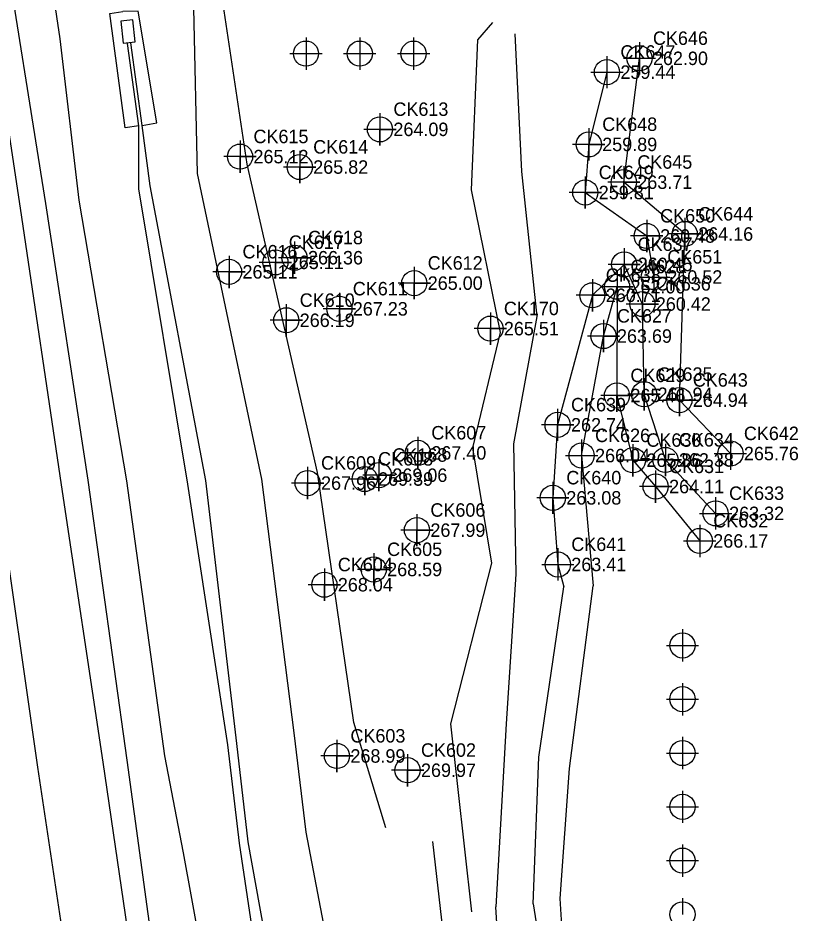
# Model space of a CAD drawing. Extents: x 1941547 to 1942851, y 663002 to 668358.
# Drawn here: x 1942636.4 to 1942781.5, y 663600.2 to 663766.6 of the extents above; entities that cross this region are included whole.
import ezdxf

# ---------------------------------------------------------------- set-up
doc = ezdxf.new("R2010")
doc.units = 0
for name, color, linetype in [('CTL GPS Vertical Cogo Elevation', 7, 'Continuous'), ('CTL NGS Vertical CELL', 7, 'Continuous'), ('Default Symbol CELL', 7, 'Continuous'), ('Exist DTM Breakline Cogo Elevation', 7, 'Continuous'), ('Exist DTM Breakline Cogo Number', 7, 'Continuous'), ('Exist DTM Breakline Cogo Point CELL', 7, 'Continuous'), ('Exist DTM Drainline Cogo Elevation', 7, 'Continuous'), ('Exist DTM QL2 LIDAR Elevation Point', 7, 'Continuous'), ('Exist Property Iron Pin Cogo Number', 7, 'Continuous'), ('Exist Roads EOP Cogo Elevation', 7, 'Continuous'), ('Exist Roads EOP Cogo Number', 7, 'Continuous'), ('Exist Roads EOP Cogo Point CELL', 7, 'Continuous'), ('Exist Roads EOT', 7, 'Continuous'), ('Exist Structure Minor Paved Ditch or Gutter', 7, 'Continuous'), ('Exist Utilities Telephone UG Cable SUE LOS C Cogo Elevation', 7, 'Continuous'), ('Exist Utilities Telephone UG FO SUE LOS C Cogo Elevation', 7, 'Continuous')]:
    doc.layers.add(name, color=color, linetype=linetype)

msp = doc.modelspace()

# ---------------------------------------------------------------- linework, layer by layer
at = {"layer": 'CTL NGS Vertical CELL'}
for points in [[(1942684.41, 663567.93), (1942677.62, 663613.22), (1942675.48, 663631.55), (1942668, 663679.97), (1942658.93, 663734.89), (1942658.92, 663746.56), (1942656.8, 663761.87)], [(1942691.99, 663527.43), (1942687.35, 663568.53), (1942679.24, 663613.49), (1942677.15, 663631.76), (1942671.36, 663680.68), (1942661.01, 663735.45), (1942659.52, 663746.66), (1942657.4, 663761.97)]]:
    msp.add_lwpolyline(points, dxfattribs=at)
at = {"layer": 'Exist DTM Breakline Cogo Number'}
for points in [[(1942752.01, 663762.12), (1942752.01, 663759.12)], [(1942745.96, 663759.55), (1942745.96, 663756.55)], [(1942749.01, 663759.12), (1942752.01, 663759.12)], [(1942752.01, 663759.12), (1942755.01, 663759.12)], [(1942752.01, 663759.12), (1942752.01, 663756.12)], [(1942742.96, 663756.55), (1942745.96, 663756.55)], [(1942745.96, 663756.55), (1942748.96, 663756.55)], [(1942745.96, 663756.55), (1942745.96, 663753.55)], [(1942754.68, 663721.47), (1942754.68, 663718.47)], [(1942751.68, 663718.47), (1942754.68, 663718.47)], [(1942754.68, 663718.47), (1942757.68, 663718.47)], [(1942754.68, 663718.47), (1942754.68, 663715.47)], [(1942741.25, 663688.29), (1942741.25, 663685.29)], [(1942768.92, 663688.66), (1942768.92, 663685.66)], [(1942738.25, 663685.29), (1942741.25, 663685.29)], [(1942741.25, 663685.29), (1942744.25, 663685.29)], [(1942741.25, 663685.29), (1942741.25, 663682.29)], [(1942765.92, 663685.66), (1942768.92, 663685.66)], [(1942768.92, 663685.66), (1942771.92, 663685.66)], [(1942768.92, 663685.66), (1942768.92, 663682.66)], [(1942766.17, 663677.54), (1942766.17, 663674.54)], [(1942763.17, 663674.54), (1942766.17, 663674.54)], [(1942766.17, 663674.54), (1942769.17, 663674.54)], [(1942766.17, 663674.54), (1942766.17, 663671.54)], [(1942763.22, 663672.42), (1942763.22, 663669.42)], [(1942760.22, 663669.42), (1942763.22, 663669.42)], [(1942763.22, 663669.42), (1942766.22, 663669.42)], [(1942763.22, 663669.42), (1942763.22, 663666.42)], [(1942736.83, 663668.05), (1942736.83, 663665.05)], [(1942733.83, 663665.05), (1942736.83, 663665.05)], [(1942736.83, 663665.05), (1942739.83, 663665.05)], [(1942736.83, 663665.05), (1942736.83, 663662.05)]]:
    msp.add_lwpolyline(points, dxfattribs=at)
for centre in [(1942752.01, 663759.12), (1942745.96, 663756.55), (1942754.68, 663718.47), (1942741.25, 663685.29), (1942768.92, 663685.66), (1942766.17, 663674.54), (1942763.22, 663669.42), (1942736.83, 663665.05)]:
    msp.add_circle(centre, 2.34, dxfattribs=at)
at = {"layer": 'Exist DTM Drainline Cogo Elevation'}
for points in [[(1942703.75, 663748.92), (1942703.75, 663742.92), (1942703.75, 663745.92), (1942706.75, 663745.92), (1942700.75, 663745.92)], [(1942703.75, 663748.92), (1942703.75, 663742.92), (1942703.75, 663745.92), (1942706.75, 663745.92), (1942700.75, 663745.92)], [(1942677.73, 663743.85), (1942677.73, 663737.85), (1942677.73, 663740.85), (1942680.73, 663740.85), (1942674.73, 663740.85)], [(1942677.73, 663743.85), (1942677.73, 663737.85), (1942677.73, 663740.85), (1942680.73, 663740.85), (1942674.73, 663740.85)], [(1942688.84, 663741.91), (1942688.84, 663735.91), (1942688.84, 663738.91), (1942691.84, 663738.91), (1942685.84, 663738.91)], [(1942688.84, 663741.91), (1942688.84, 663735.91), (1942688.84, 663738.91), (1942691.84, 663738.91), (1942685.84, 663738.91)], [(1942687.87, 663725.06), (1942687.87, 663719.06), (1942687.87, 663722.06), (1942690.87, 663722.06), (1942684.87, 663722.06)], [(1942687.87, 663725.06), (1942687.87, 663719.06), (1942687.87, 663722.06), (1942690.87, 663722.06), (1942684.87, 663722.06)], [(1942684.3, 663724.2), (1942684.3, 663718.2), (1942684.3, 663721.2), (1942687.3, 663721.2), (1942681.3, 663721.2)], [(1942684.3, 663724.2), (1942684.3, 663718.2), (1942684.3, 663721.2), (1942687.3, 663721.2), (1942681.3, 663721.2)], [(1942675.69, 663722.43), (1942675.69, 663716.43), (1942675.69, 663719.43), (1942678.69, 663719.43), (1942672.69, 663719.43)], [(1942675.69, 663722.43), (1942675.69, 663716.43), (1942675.69, 663719.43), (1942678.69, 663719.43), (1942672.69, 663719.43)], [(1942710.13, 663720.34), (1942710.13, 663714.34), (1942710.13, 663717.34), (1942713.13, 663717.34), (1942707.13, 663717.34)], [(1942710.13, 663720.34), (1942710.13, 663714.34), (1942710.13, 663717.34), (1942713.13, 663717.34), (1942707.13, 663717.34)], [(1942696.2, 663715.56), (1942696.2, 663709.56), (1942696.2, 663712.56), (1942699.2, 663712.56), (1942693.2, 663712.56)], [(1942696.2, 663715.56), (1942696.2, 663709.56), (1942696.2, 663712.56), (1942699.2, 663712.56), (1942693.2, 663712.56)], [(1942686.33, 663713.43), (1942686.33, 663707.43), (1942686.33, 663710.43), (1942689.33, 663710.43), (1942683.33, 663710.43)], [(1942686.33, 663713.43), (1942686.33, 663707.43), (1942686.33, 663710.43), (1942689.33, 663710.43), (1942683.33, 663710.43)], [(1942724.29, 663711.88), (1942724.29, 663705.88), (1942724.29, 663708.88), (1942727.29, 663708.88), (1942721.29, 663708.88)], [(1942710.8, 663688.78), (1942710.8, 663682.78), (1942710.8, 663685.78), (1942713.8, 663685.78), (1942707.8, 663685.78)], [(1942710.8, 663688.78), (1942710.8, 663682.78), (1942710.8, 663685.78), (1942713.8, 663685.78), (1942707.8, 663685.78)], [(1942703.55, 663684.64), (1942703.55, 663678.64), (1942703.55, 663681.64), (1942706.55, 663681.64), (1942700.55, 663681.64)], [(1942690.3, 663683.17), (1942690.3, 663677.17), (1942690.3, 663680.17), (1942693.3, 663680.17), (1942687.3, 663680.17)], [(1942700.91, 663683.93), (1942700.91, 663677.93), (1942700.91, 663680.93), (1942703.91, 663680.93), (1942697.91, 663680.93)], [(1942700.91, 663683.93), (1942700.91, 663677.93), (1942700.91, 663680.93), (1942703.91, 663680.93), (1942697.91, 663680.93)], [(1942710.63, 663674.42), (1942710.63, 663668.42), (1942710.63, 663671.42), (1942713.63, 663671.42), (1942707.63, 663671.42)], [(1942710.63, 663674.42), (1942710.63, 663668.42), (1942710.63, 663671.42), (1942713.63, 663671.42), (1942707.63, 663671.42)], [(1942702.59, 663667.12), (1942702.59, 663661.12), (1942702.59, 663664.12), (1942705.59, 663664.12), (1942699.59, 663664.12)], [(1942702.59, 663667.12), (1942702.59, 663661.12), (1942702.59, 663664.12), (1942705.59, 663664.12), (1942699.59, 663664.12)], [(1942693.42, 663664.28), (1942693.42, 663658.28), (1942693.42, 663661.28), (1942696.42, 663661.28), (1942690.42, 663661.28)], [(1942693.42, 663664.28), (1942693.42, 663658.28), (1942693.42, 663661.28), (1942696.42, 663661.28), (1942690.42, 663661.28)], [(1942695.76, 663632.45), (1942695.76, 663626.45), (1942695.76, 663629.45), (1942698.76, 663629.45), (1942692.76, 663629.45)], [(1942695.76, 663632.45), (1942695.76, 663626.45), (1942695.76, 663629.45), (1942698.76, 663629.45), (1942692.76, 663629.45)], [(1942708.88, 663629.8), (1942708.88, 663623.8), (1942708.88, 663626.8), (1942711.88, 663626.8), (1942705.88, 663626.8)], [(1942708.88, 663629.8), (1942708.88, 663623.8), (1942708.88, 663626.8), (1942711.88, 663626.8), (1942705.88, 663626.8)]]:
    msp.add_lwpolyline(points, dxfattribs=at)
for centre in [(1942703.75, 663745.92), (1942703.75, 663745.92), (1942677.73, 663740.85), (1942677.73, 663740.85), (1942688.84, 663738.91), (1942688.84, 663738.91), (1942687.87, 663722.06), (1942687.87, 663722.06), (1942684.3, 663721.2), (1942684.3, 663721.2), (1942675.69, 663719.43), (1942675.69, 663719.43), (1942710.13, 663717.34), (1942710.13, 663717.34), (1942696.2, 663712.56), (1942696.2, 663712.56), (1942686.33, 663710.43), (1942686.33, 663710.43), (1942724.29, 663708.88), (1942710.8, 663685.78), (1942710.8, 663685.78), (1942700.91, 663680.93), (1942700.91, 663680.93), (1942703.55, 663681.64), (1942690.3, 663680.17), (1942710.63, 663671.42), (1942710.63, 663671.42), (1942702.59, 663664.12), (1942702.59, 663664.12), (1942693.42, 663661.28), (1942693.42, 663661.28), (1942695.76, 663629.45), (1942695.76, 663629.45), (1942708.88, 663626.8), (1942708.88, 663626.8)]:
    msp.add_circle(centre, 2.34, dxfattribs=at)
at = {"layer": 'Exist DTM QL2 LIDAR Elevation Point'}
for points in [[(1942690, 663763), (1942690, 663760)], [(1942700, 663763), (1942700, 663760)], [(1942710, 663763), (1942710, 663760)], [(1942687, 663760), (1942690, 663760)], [(1942690, 663760), (1942693, 663760)], [(1942690, 663760), (1942690, 663757)], [(1942697, 663760), (1942700, 663760)], [(1942700, 663760), (1942703, 663760)], [(1942700, 663760), (1942700, 663757)], [(1942707, 663760), (1942710, 663760)], [(1942710, 663760), (1942713, 663760)], [(1942710, 663760), (1942710, 663757)], [(1942760, 663653), (1942760, 663650)], [(1942757, 663650), (1942760, 663650)], [(1942760, 663650), (1942763, 663650)], [(1942760, 663650), (1942760, 663647)], [(1942760, 663643), (1942760, 663640)], [(1942757, 663640), (1942760, 663640)], [(1942760, 663640), (1942763, 663640)], [(1942760, 663640), (1942760, 663637)], [(1942760, 663633), (1942760, 663630)], [(1942757, 663630), (1942760, 663630)], [(1942760, 663630), (1942763, 663630)], [(1942760, 663630), (1942760, 663627)], [(1942760, 663623), (1942760, 663620)], [(1942757, 663620), (1942760, 663620)], [(1942760, 663620), (1942763, 663620)], [(1942760, 663620), (1942760, 663617)], [(1942760, 663613), (1942760, 663610)], [(1942757, 663610), (1942760, 663610)], [(1942760, 663610), (1942763, 663610)], [(1942760, 663610), (1942760, 663607)], [(1942760, 663603), (1942760, 663600)]]:
    msp.add_lwpolyline(points, dxfattribs=at)
for centre in [(1942690, 663760), (1942700, 663760), (1942710, 663760), (1942760, 663650), (1942760, 663640), (1942760, 663630), (1942760, 663620), (1942760, 663610), (1942760, 663600)]:
    msp.add_circle(centre, 2.34, dxfattribs=at)
at = {"layer": 'Exist Property Iron Pin Cogo Number'}
msp.add_lwpolyline([(1942535.15, 664241.51), (1942545.15, 664190.98), (1942554.98, 664140.31), (1942564.32, 664090.5), (1942574.04, 664037.16), (1942583.23, 663987.29), (1942591.6, 663938.59), (1942600.26, 663885.84), (1942608.93, 663833.98), (1942616.95, 663781.65), (1942624.84, 663729.94), (1942632.77, 663678.03), (1942640.07, 663627.4), (1942648.8, 663569.13)], dxfattribs=at)
at = {"layer": 'Exist Roads EOP Cogo Number'}
for points in [[(1942742.58, 663746.12), (1942742.58, 663740.12), (1942742.58, 663743.12), (1942745.58, 663743.12), (1942739.58, 663743.12)], [(1942749.1, 663739.1), (1942749.1, 663733.1), (1942749.1, 663736.1), (1942752.1, 663736.1), (1942746.1, 663736.1)], [(1942741.93, 663737.18), (1942741.93, 663731.18), (1942741.93, 663734.18), (1942744.93, 663734.18), (1942738.93, 663734.18)], [(1942760.42, 663729.47), (1942760.42, 663723.47), (1942760.42, 663726.47), (1942763.42, 663726.47), (1942757.42, 663726.47)], [(1942753.35, 663729.1), (1942753.35, 663723.1), (1942753.35, 663726.1), (1942756.35, 663726.1), (1942750.35, 663726.1)], [(1942749.16, 663723.82), (1942749.16, 663717.82), (1942749.16, 663720.82), (1942752.16, 663720.82), (1942746.16, 663720.82)], [(1942747.83, 663719.67), (1942747.83, 663713.67), (1942747.83, 663716.67), (1942750.83, 663716.67), (1942744.83, 663716.67)], [(1942743.24, 663718.07), (1942743.24, 663712.07), (1942743.24, 663715.07), (1942746.24, 663715.07), (1942740.24, 663715.07)], [(1942752.54, 663716.45), (1942752.54, 663710.45), (1942752.54, 663713.45), (1942755.54, 663713.45), (1942749.54, 663713.45)], [(1942745.32, 663710.5), (1942745.32, 663704.5), (1942745.32, 663707.5), (1942748.32, 663707.5), (1942742.32, 663707.5)], [(1942747.82, 663699.44), (1942747.82, 663693.44), (1942747.82, 663696.44), (1942750.82, 663696.44), (1942744.82, 663696.44)], [(1942752.87, 663699.68), (1942752.87, 663693.68), (1942752.87, 663696.68), (1942755.87, 663696.68), (1942749.87, 663696.68)], [(1942759.42, 663698.59), (1942759.42, 663692.59), (1942759.42, 663695.59), (1942762.42, 663695.59), (1942756.42, 663695.59)], [(1942736.78, 663694), (1942736.78, 663688), (1942736.78, 663691), (1942739.78, 663691), (1942733.78, 663691)], [(1942750.79, 663687.42), (1942750.79, 663681.42), (1942750.79, 663684.42), (1942753.79, 663684.42), (1942747.79, 663684.42)], [(1942756.83, 663687.47), (1942756.83, 663681.47), (1942756.83, 663684.47), (1942759.83, 663684.47), (1942753.83, 663684.47)], [(1942755.01, 663682.53), (1942755.01, 663676.53), (1942755.01, 663679.53), (1942758.01, 663679.53), (1942752.01, 663679.53)], [(1942735.9, 663680.43), (1942735.9, 663674.43), (1942735.9, 663677.43), (1942738.9, 663677.43), (1942732.9, 663677.43)]]:
    msp.add_lwpolyline(points, dxfattribs=at)
for centre in [(1942742.58, 663743.12), (1942749.1, 663736.1), (1942741.93, 663734.18), (1942753.35, 663726.1), (1942760.42, 663726.47), (1942749.16, 663720.82), (1942747.83, 663716.67), (1942743.24, 663715.07), (1942752.54, 663713.45), (1942745.32, 663707.5), (1942747.82, 663696.44), (1942752.87, 663696.68), (1942759.42, 663695.59), (1942736.78, 663691), (1942750.79, 663684.42), (1942756.83, 663684.47), (1942755.01, 663679.53), (1942735.9, 663677.43)]:
    msp.add_circle(centre, 2.34, dxfattribs=at)
at = {"layer": 'Exist Roads EOT'}
msp.add_lwpolyline([(1942546.97, 664243.63), (1942556.97, 664193.32), (1942566.94, 664142.09), (1942576.07, 664092.72), (1942586.16, 664038.02), (1942595.11, 663989.06), (1942603.48, 663940.87), (1942612.18, 663887.97), (1942620.88, 663835.09), (1942628.9, 663783.73), (1942636.85, 663731.29), (1942644.5, 663679.83), (1942652.2, 663628.27), (1942660.61, 663571.1)], dxfattribs=at)
at = {"layer": 'Exist Structure Minor Paved Ditch or Gutter'}
for points in [[(1942658.92, 663746.56), (1942656.39, 663746.17), (1942653.53, 663767.46), (1942655.94, 663767.8)], [(1942659.52, 663746.66), (1942662.27, 663747.11), (1942658.78, 663767.89), (1942655.94, 663767.8)]]:
    msp.add_lwpolyline(points, dxfattribs=at)
at = {"layer": 'Exist Utilities Telephone UG Cable SUE LOS C Cogo Elevation'}
msp.add_lwpolyline([(1942551.4, 664244.16), (1942561.16, 664194.29), (1942571.17, 664142.93), (1942580.34, 664093.62), (1942590.26, 664039.1), (1942599.47, 663989.58), (1942608.09, 663941.73), (1942616.79, 663888.57), (1942625.47, 663835.77), (1942633.35, 663783.87), (1942641.57, 663732.16), (1942649.42, 663680.73), (1942656.69, 663628.65), (1942664.5, 663571.56), (1942664.5, 663571.37)], dxfattribs=at)
at = {"layer": 'Exist Utilities Telephone UG FO SUE LOS C Cogo Elevation'}
for p, q in [((1942741.25, 663685.29), (1942743.38, 663661.05)), ((1942736.83, 663665.05), (1942737.96, 663660.88))]:
    msp.add_line(p, q, dxfattribs=at)
for points in [[(1942698.67, 663570.27), (1942690.05, 663615.32), (1942687.8, 663633.74), (1942681.77, 663680.9), (1942669.81, 663737.7), (1942669.16, 663768.43), (1942660.74, 663785.94), (1942654.22, 663840.51), (1942659.2, 663867.37), (1942662.57, 663894.02), (1942660.53, 663948.94), (1942653.89, 663997.65), (1942646.16, 664051.26), (1942643.52, 664103.09), (1942633.42, 664153.43), (1942621.98, 664209.98), (1942611.29, 664238.27), (1942628.17, 664250.61)], [(1942667.2, 663611.44), (1942663.75, 663629.46), (1942656.66, 663680.59), (1942647.81, 663732.78), (1942644.32, 663762.75), (1942641.56, 663781.09), (1942633.01, 663836.17), (1942623.47, 663889.48), (1942614.38, 663941.8), (1942605.73, 663991.44), (1942595.41, 664040.38), (1942587.5, 664094.08), (1942579.23, 664144.8), (1942568.86, 664196.24), (1942564.72, 664235.72)], [(1942667.2, 663611.44), (1942663.75, 663629.46), (1942656.66, 663680.59), (1942647.81, 663732.78), (1942644.32, 663762.75), (1942641.56, 663781.09), (1942633.01, 663836.17), (1942623.47, 663889.48), (1942614.38, 663941.8), (1942605.73, 663991.44), (1942595.41, 664040.38), (1942587.5, 664094.08), (1942579.23, 664144.8), (1942568.86, 664196.24)], [(1942704.84, 663616.1), (1942698.88, 663635.66), (1942692.14, 663682.12), (1942679.09, 663739.47), (1942674.62, 663769.17), (1942670.34, 663787.84), (1942660.41, 663841.9)], [(1942724.65, 663765.77), (1942721.86, 663762.55), (1942720.7, 663734.69), (1942726.1, 663708.15), (1942720.97, 663686.75), (1942724.48, 663665.3), (1942716.84, 663635.41), (1942720.75, 663600.49)], [(1942728.84, 663763.67), (1942730.08, 663738.06), (1942732.95, 663711.15), (1942728.58, 663687.45), (1942729.04, 663663.24), (1942727.24, 663635.45), (1942725.3, 663601.43)], [(1942768.92, 663685.66), (1942759.42, 663695.59), (1942760.42, 663726.47), (1942749.1, 663736.1), (1942752.01, 663759.12)], [(1942768.92, 663685.66), (1942759.42, 663695.59), (1942760.42, 663726.47), (1942749.1, 663736.1), (1942752.01, 663759.12)], [(1942745.96, 663756.55), (1942742.58, 663743.12), (1942741.93, 663734.18), (1942753.35, 663726.1), (1942754.68, 663718.47)], [(1942745.96, 663756.55), (1942742.58, 663743.12), (1942741.93, 663734.18), (1942753.35, 663726.1), (1942754.68, 663718.47)], [(1942766.17, 663674.54), (1942756.83, 663684.47), (1942752.87, 663696.68), (1942752.54, 663713.45), (1942749.16, 663720.82), (1942743.24, 663715.07), (1942736.78, 663691), (1942735.9, 663677.43), (1942736.83, 663665.05)], [(1942766.17, 663674.54), (1942756.83, 663684.47), (1942752.87, 663696.68), (1942752.54, 663713.45), (1942749.16, 663720.82), (1942743.24, 663715.07), (1942736.78, 663691), (1942735.9, 663677.43), (1942736.83, 663665.05)], [(1942741.25, 663685.29), (1942745.32, 663707.5), (1942747.83, 663716.67), (1942747.82, 663696.44), (1942750.79, 663684.42), (1942755.01, 663679.53), (1942763.22, 663669.42)], [(1942741.25, 663685.29), (1942745.32, 663707.5), (1942747.83, 663716.67), (1942747.82, 663696.44), (1942750.79, 663684.42), (1942755.01, 663679.53), (1942763.22, 663669.42)], [(1942737.24, 663602.98), (1942739.01, 663627.14), (1942743.38, 663661.05)], [(1942732.21, 663601.96), (1942733.3, 663629.2), (1942737.96, 663660.88)], [(1942713.52, 663613.55), (1942719.3, 663563.18), (1942718.02, 663550.78), (1942723.76, 663536.03), (1942731.18, 663532.11), (1942741.65, 663538.34), (1942743.22, 663567.63), (1942738.46, 663584.14), (1942737.24, 663602.98)], [(1942701.8, 663523.04), (1942693.52, 663518.71), (1942681.29, 663525.16), (1942675.34, 663566.99), (1942667.2, 663611.44)], [(1942732.21, 663601.96), (1942735, 663584.37), (1942735.95, 663565.31), (1942734.24, 663551.32), (1942734.17, 663538.46), (1942727.43, 663539.63), (1942727.9, 663553.6), (1942728.64, 663564.46), (1942726.5, 663582.2), (1942725.3, 663601.43)]]:
    msp.add_lwpolyline(points, dxfattribs=at)
msp.add_lwpolyline([(1942655.59, 663766.04), (1942656.02, 663761.96), (1942658.24, 663762.2), (1942657.82, 663766.27)], close=True, dxfattribs=at)

# ---------------------------------------------------------------- texts
at = {"layer": 'CTL GPS Vertical Cogo Elevation'}
for s, p in [('CK613', (1942706.25, 663748.42)), ('CK615', (1942680.23, 663743.35)), ('CK614', (1942691.34, 663741.41)), ('CK617', (1942686.8, 663723.7)), ('CK618', (1942690.37, 663724.56)), ('CK616', (1942678.19, 663721.93)), ('CK612', (1942712.63, 663719.84)), ('CK611', (1942698.7, 663715.06)), ('CK610', (1942688.83, 663712.93)), ('CK170', (1942726.79, 663711.38)), ('CK607', (1942713.3, 663688.28)), ('CK608', (1942703.41, 663683.43)), ('CK168', (1942706.05, 663684.14)), ('CK609', (1942692.8, 663682.67)), ('CK606', (1942713.13, 663673.92)), ('CK605', (1942705.09, 663666.62)), ('CK604', (1942695.92, 663663.78)), ('CK603', (1942698.26, 663631.95)), ('CK602', (1942711.38, 663629.3))]:
    msp.add_text(s, height=2.5, dxfattribs=at).set_placement(p)
at = {"layer": 'Default Symbol CELL'}
for s, p in [('262.90', (1942754.51, 663757.87)), ('259.44', (1942748.46, 663755.3)), ('260.52', (1942757.18, 663717.22)), ('266.04', (1942743.75, 663684.04)), ('265.76', (1942771.42, 663684.41)), ('263.32', (1942768.67, 663673.29)), ('266.17', (1942765.72, 663668.17)), ('263.41', (1942739.33, 663663.8))]:
    msp.add_text(s, height=2.5, dxfattribs=at).set_placement(p)
at = {"layer": 'Exist DTM Breakline Cogo Elevation'}
for s, p in [('CK646', (1942754.51, 663761.62)), ('CK647', (1942748.46, 663759.05)), ('CK651', (1942757.18, 663720.97)), ('CK626', (1942743.75, 663687.79)), ('CK642', (1942771.42, 663688.16)), ('CK633', (1942768.67, 663677.04)), ('CK632', (1942765.72, 663671.92)), ('CK641', (1942739.33, 663667.55))]:
    msp.add_text(s, height=2.5, dxfattribs=at).set_placement(p)
at = {"layer": 'Exist DTM Breakline Cogo Point CELL'}
for s, p in [('259.89', (1942745.08, 663741.87)), ('263.71', (1942751.6, 663734.85)), ('259.81', (1942744.43, 663732.93)), ('264.16', (1942762.92, 663725.22)), ('260.48', (1942755.85, 663724.85)), ('260.45', (1942751.66, 663719.57)), ('262.00', (1942750.33, 663715.42)), ('260.71', (1942745.74, 663713.83)), ('260.42', (1942755.04, 663712.2)), ('263.69', (1942747.82, 663706.25)), ('265.46', (1942750.32, 663695.19)), ('261.94', (1942755.37, 663695.43)), ('264.94', (1942761.92, 663694.34)), ('262.74', (1942739.28, 663689.75)), ('265.86', (1942753.29, 663683.17)), ('262.38', (1942759.33, 663683.22)), ('264.11', (1942757.51, 663678.28)), ('263.08', (1942738.4, 663676.18))]:
    msp.add_text(s, height=2.5, dxfattribs=at).set_placement(p)
at = {"layer": 'Exist Roads EOP Cogo Elevation'}
for s, p in [('CK648', (1942745.08, 663745.62)), ('CK645', (1942751.6, 663738.6)), ('CK649', (1942744.43, 663736.68)), ('CK650', (1942755.85, 663728.6)), ('CK644', (1942762.92, 663728.97)), ('CK637', (1942751.66, 663723.32)), ('CK628', (1942750.33, 663719.17)), ('CK638', (1942745.74, 663717.58)), ('CK636', (1942755.04, 663715.95)), ('CK627', (1942747.82, 663710)), ('CK629', (1942750.32, 663698.94)), ('CK635', (1942755.37, 663699.18)), ('CK643', (1942761.92, 663698.09)), ('CK639', (1942739.28, 663693.5)), ('CK630', (1942753.29, 663686.92)), ('CK634', (1942759.33, 663686.97)), ('CK631', (1942757.51, 663682.03)), ('CK640', (1942738.4, 663679.93))]:
    msp.add_text(s, height=2.5, dxfattribs=at).set_placement(p)
at = {"layer": 'Exist Roads EOP Cogo Point CELL'}
for s, p in [('264.09', (1942706.25, 663744.67)), ('265.12', (1942680.23, 663739.6)), ('265.82', (1942691.34, 663737.66)), ('266.36', (1942690.37, 663720.81)), ('265.11', (1942686.8, 663719.95)), ('265.11', (1942678.19, 663718.18)), ('265.00', (1942712.63, 663716.09)), ('267.23', (1942698.7, 663711.31)), ('266.19', (1942688.83, 663709.18)), ('265.51', (1942726.79, 663707.63)), ('267.40', (1942713.3, 663684.53)), ('269.06', (1942706.05, 663680.39)), ('267.96', (1942692.8, 663678.92)), ('269.39', (1942703.41, 663679.68)), ('267.99', (1942713.13, 663670.17)), ('268.59', (1942705.09, 663662.87)), ('268.04', (1942695.92, 663660.03)), ('268.99', (1942698.26, 663628.2)), ('269.97', (1942711.38, 663625.55))]:
    msp.add_text(s, height=2.5, dxfattribs=at).set_placement(p)

doc.saveas('drawing.dxf')
